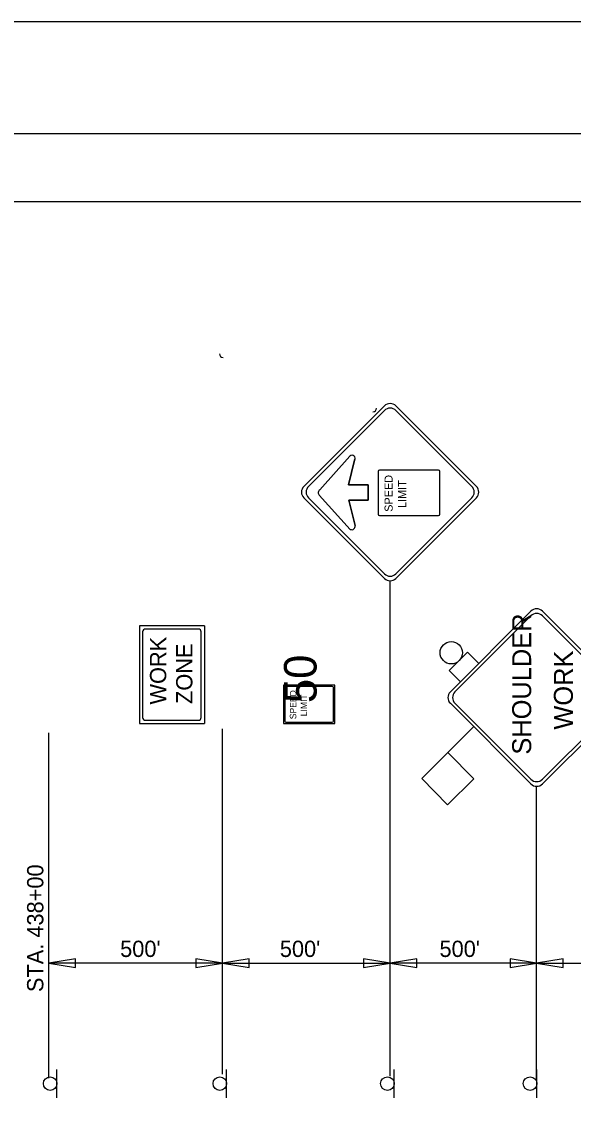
# Model space of a CAD drawing. Extents: x 2155255 to 2162649, y 140388 to 141878.
# Drawn here: x 2156509.2 to 2156712.5, y 141189.8 to 141588.2 of the extents above; entities that cross this region are included whole.
import ezdxf

# ---------------------------------------------------------------- set-up
doc = ezdxf.new("R2010")
doc.units = 0
for name, color, linetype in [('5', 7, 'Continuous'), ('Default', 7, 'Continuous'), ('PR_Dimensions1', 7, 'Continuous'), ('PR_Traffic_Control_Devices_Temp', 7, 'Continuous'), ('PR_Traffic_Temp_Txt', 7, 'Continuous'), ('SHT_Plot_Shape_Full', 7, 'Continuous'), ('SHT_Plot_Shape_Half', 7, 'Continuous'), ('SHT_Sheet_Border', 7, 'Continuous')]:
    doc.layers.add(name, color=color, linetype=linetype)

# ---------------------------------------------------------------- blocks, each defined once
blk = doc.blocks.new('FLSHFLAG')
at = {"layer": 'Default'}
for p, q in [((-1.202, 14.125), (0.838, 16.147)), ((0.838, 16.147), (4.9, 12.085)), ((0.819, 12.085), (-1.202, 14.125)), ((0.819, 12.085), (2.86, 14.106)), ((9.258, 14.004), (8.403, 13.149)), ((9.258, 14.004), (10.685, 12.576)), ((10.685, 12.576), (9.831, 11.722))]:
    blk.add_line(p, q, dxfattribs=at)
blk.add_circle((10.653, 13.836), 0.873, dxfattribs=at)
blk = doc.blocks.new('R2-1e')
at = {"layer": 'Default'}
for p, q in [((3, 4), (0, 4)), ((0, 4), (0, 0)), ((0.1, 3.812), (0.1, 0.187)), ((2.812, 3.9), (0.187, 3.9)), ((2.9, 0.187), (2.9, 3.812)), ((3, 0), (3, 4)), ((0, 0), (3, 0)), ((0.187, 0.1), (2.812, 0.1))]:
    blk.add_line(p, q, dxfattribs=at)
for centre, start, end in [((0.187, 3.812), 90, 180), ((2.812, 3.812), 0, 90), ((0.187, 0.187), 180, 270), ((2.812, 0.187), 270, 0)]:
    blk.add_arc(centre, 0.0875, start, end, dxfattribs=at)
for s, p in [('SPEED', (0.333, 3)), ('LIMIT', (0.567, 2.167))]:
    blk.add_text(s, height=0.5, dxfattribs=at).set_placement(p)
blk = doc.blocks.new('CS-14E')
at = {"layer": 'Default'}
for p, q in [((7.62, 2.54), (0, 2.54)), ((0, 2.54), (0, -2.54)), ((7.62, -2.54), (7.62, 2.54)), ((0.254, 2.064), (0.254, -2.064)), ((7.144, 2.286), (0.476, 2.286)), ((7.366, -2.064), (7.366, 2.064)), ((0.476, -2.286), (7.144, -2.286)), ((7.62, -2.54), (0, -2.54))]:
    blk.add_line(p, q, dxfattribs=at)
for centre, start, end in [((0.476, 2.064), 90, 180), ((7.144, 2.064), 0, 90), ((0.476, -2.064), 180, 270), ((7.144, -2.064), 270, 0)]:
    blk.add_arc(centre, 0.222, start, end, dxfattribs=at)
for s, p in [('WORK', (1.482, 0.444)), ('ZONE', (1.526, -1.598))]:
    blk.add_text(s, height=1.27, dxfattribs=at).set_placement(p)
blk = doc.blocks.new('TCSIGN')
at = {"layer": 'Default'}
blk.add_line((5.26, 2.5), (-5.26, 2.5), dxfattribs=at)
blk.add_circle((0, 0), 2.5, dxfattribs=at)
blk = doc.blocks.new('Arrowhd')
at = {"layer": 'Default'}
blk.add_lwpolyline([(0.318, -0.053), (0.318, 0.053), (0, 0)], close=True, dxfattribs=at)
blk = doc.blocks.new('W3-5_1')
at = {"layer": '5'}
for p, q in [((0.808, 7.633), (6.735, 13.56)), ((13.56, 7.633), (7.633, 13.56)), ((6.735, 0.808), (0.808, 6.735)), ((7.633, 0.808), (13.56, 6.735))]:
    blk.add_line(p, q, dxfattribs=at)
for centre, start, end in [((7.184, 13.111), 45, 135), ((1.257, 7.184), 135, 225), ((13.111, 7.184), 315, 45), ((7.184, 1.257), 225, 315)]:
    blk.add_arc(centre, 0.635, start, end, dxfattribs=at)
at = {"layer": 'Default'}
for p, q in [((0.448, 7.633), (6.735, 13.919)), ((13.919, 7.633), (7.633, 13.919)), ((6.95, 12.723), (4.277, 10.304)), ((9.984, 10.322), (7.366, 12.687)), ((5.352, 8.019), (5.352, 3.415)), ((8.797, 8.13), (5.464, 8.13)), ((8.908, 3.415), (8.908, 8.019)), ((6.735, 0.449), (0.448, 6.735)), ((7.633, 0.449), (13.919, 6.735)), ((5.464, 3.304), (8.797, 3.304))]:
    blk.add_line(p, q, dxfattribs=at)
for points in [[(4.277, 10.304), (6.95, 12.723)], [(7.366, 12.687), (9.984, 10.322)], [(4.584, 9.924), (6.553, 10.412), (6.553, 8.913), (7.745, 8.913), (7.745, 10.448), (9.677, 9.96)], [(9.677, 9.96), (7.745, 10.448), (7.745, 8.913), (6.553, 8.913), (6.553, 10.412), (4.584, 9.924)]]:
    blk.add_lwpolyline(points, dxfattribs=at)
for centre, radius, start, end in [((7.184, 13.47), 0.635, 45, 135), ((7.141, 12.512), 0.285, 37.91416, 132.14933), ((7.141, 12.512), 0.285, 37.91416, 132.14933), ((4.519, 10.186), 0.269, 154.09026, 283.9085), ((4.519, 10.186), 0.269, 154.09026, 283.9085), ((9.825, 10.146), 0.237, 231.34169, 47.91235), ((9.825, 10.146), 0.237, 231.34169, 47.91235), ((0.897, 7.184), 0.635, 135, 225), ((5.464, 8.019), 0.111, 90, 180), ((8.797, 8.019), 0.111, 0, 90), ((13.47, 7.184), 0.635, 315, 45), ((5.464, 3.415), 0.111, 180, 270), ((8.797, 3.415), 0.111, 270, 0), ((7.184, 0.898), 0.635, 225, 315)]:
    blk.add_arc(centre, radius, start, end, dxfattribs=at)
for s, p in [('SPEED', (5.649, 6.987)), ('LIMIT', (5.945, 5.929))]:
    blk.add_text(s, height=0.635, dxfattribs=at).set_placement(p)
blk = doc.blocks.new('CW21-5')
at = {"layer": '5'}
for p, q in [((0.318, 3.005), (2.651, 5.339)), ((5.338, 3.005), (3.005, 5.339)), ((2.651, 0.318), (0.318, 2.652)), ((3.005, 0.318), (5.338, 2.652))]:
    blk.add_line(p, q, dxfattribs=at)
for centre, start, end in [((2.828, 5.162), 45, 135), ((0.495, 2.828), 135, 225), ((5.162, 2.828), 315, 45), ((2.828, 0.495), 225, 315)]:
    blk.add_arc(centre, 0.25, start, end, dxfattribs=at)
at = {"layer": 'Default'}
for p, q in [((0.177, 3.005), (2.651, 5.48)), ((5.48, 3.005), (3.005, 5.48)), ((2.651, 0.177), (0.177, 2.652)), ((3.005, 0.177), (5.48, 2.652))]:
    blk.add_line(p, q, dxfattribs=at)
for centre, start, end in [((2.828, 5.303), 45, 135), ((0.353, 2.828), 135, 225), ((5.303, 2.828), 315, 45), ((2.828, 0.354), 225, 315)]:
    blk.add_arc(centre, 0.25, start, end, dxfattribs=at)
for s, p in [('SHOULDER', (1.076, 2.998)), ('WORK', (1.843, 1.717))]:
    blk.add_text(s, height=0.5833, dxfattribs=at).set_placement(p)

msp = doc.modelspace()

# ---------------------------------------------------------------- linework, layer by layer
at = {"layer": 'Default'}
for centre, start, end in [((2156583.39, 141465.7), 180, 270), ((2156638.63, 141445.67), 270, 0)]:
    msp.add_arc(centre, 1.33, start, end, dxfattribs=at)
at = {"layer": 'PR_Dimensions1'}
for p, q in [((2156644.96, 141199.49), (2156644.96, 141382.09)), ((2156519.23, 141198.77), (2156519.23, 141326.01)), ((2156583.17, 141200.21), (2156583.17, 141327.45)), ((2156698.96, 141198.77), (2156698.96, 141306.49)), ((2156583.17, 141241.15), (2156519.23, 141241.15)), ((2156583.17, 141241.15), (2156644.96, 141241.15)), ((2156698.96, 141241.15), (2156644.96, 141241.15)), ((2156698.96, 141241.15), (2156758.68, 141241.15))]:
    msp.add_line(p, q, dxfattribs=at)
at = {"layer": 'SHT_Plot_Shape_Full'}
msp.add_lwpolyline([(2156155.34, 141588.17), (2157955.34, 141588.17), (2157955.34, 140388.17), (2156155.34, 140388.17)], close=True, dxfattribs=at)
at = {"layer": 'SHT_Plot_Shape_Half'}
msp.add_lwpolyline([(2156237.22, 141546.92), (2157937.22, 141546.92), (2157937.22, 140446.92), (2156237.22, 140446.92)], close=True, dxfattribs=at)
at = {"layer": 'SHT_Sheet_Border'}
msp.add_lwpolyline([(2157909.72, 140471.92), (2156334.72, 140471.92), (2156334.72, 141521.92), (2157909.72, 141521.92)], close=True, dxfattribs=at)

# ---------------------------------------------------------------- block references
at = {"layer": 'PR_Dimensions1', "xscale": 30.761459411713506, "yscale": 30.761459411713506}
for p in [(2156519.23, 141241.15), (2156583.17, 141241.15), (2156644.96, 141241.15), (2156698.96, 141241.15)]:
    msp.add_blockref('Arrowhd', p, dxfattribs=at)
at = {"layer": 'PR_Dimensions1', "xscale": 30.761459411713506, "yscale": 30.761459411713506, "rotation": 180}
for p in [(2156583.17, 141241.15), (2156644.96, 141241.15), (2156698.96, 141241.15)]:
    msp.add_blockref('Arrowhd', p, dxfattribs=at)
at = {"layer": 'PR_Traffic_Control_Devices_Temp', "rotation": 90}
for name, p, xscale, yscale in [('W3-5_1', (2156678.88, 141380.84), 4.72, 4.72), ('CW21-5', (2156732.92, 141305.1), 12, 12), ('CS-14E', (2156564.54, 141329.47), 4.7244, 4.7244), ('FLSHFLAG', (2156732.87, 141305.23), 4.7244, 4.7244), ('R2-1e', (2156624.54, 141329.47), 4.7244, 4.7244)]:
    msp.add_blockref(name, p, dxfattribs=dict(at, xscale=xscale, yscale=yscale))
at = {"layer": 'PR_Traffic_Control_Devices_Temp', "rotation": -90.00000000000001}
for p in [(2156519.68, 141196.74), (2156582.19, 141196.74), (2156643.97, 141196.74), (2156696.54, 141196.74)]:
    msp.add_blockref('TCSIGN', p, dxfattribs=at)

# ---------------------------------------------------------------- texts
at = {"layer": 'PR_Traffic_Control_Devices_Temp'}
msp.add_text('50', height=12, rotation=90, dxfattribs=at).set_placement((2156617.85, 141337))
at = {"layer": 'PR_Traffic_Temp_Txt'}
for s, rotation, p in [('STA. 438+00', 90, (2156517.16, 141230.48)), ("500'", 360, (2156545.46, 141243.42)), ("500'", 360, (2156604.31, 141243.42)), ("500'", 360, (2156663.15, 141243.42))]:
    msp.add_text(s, height=6, rotation=rotation, dxfattribs=at).set_placement(p)

doc.saveas('drawing.dxf')
